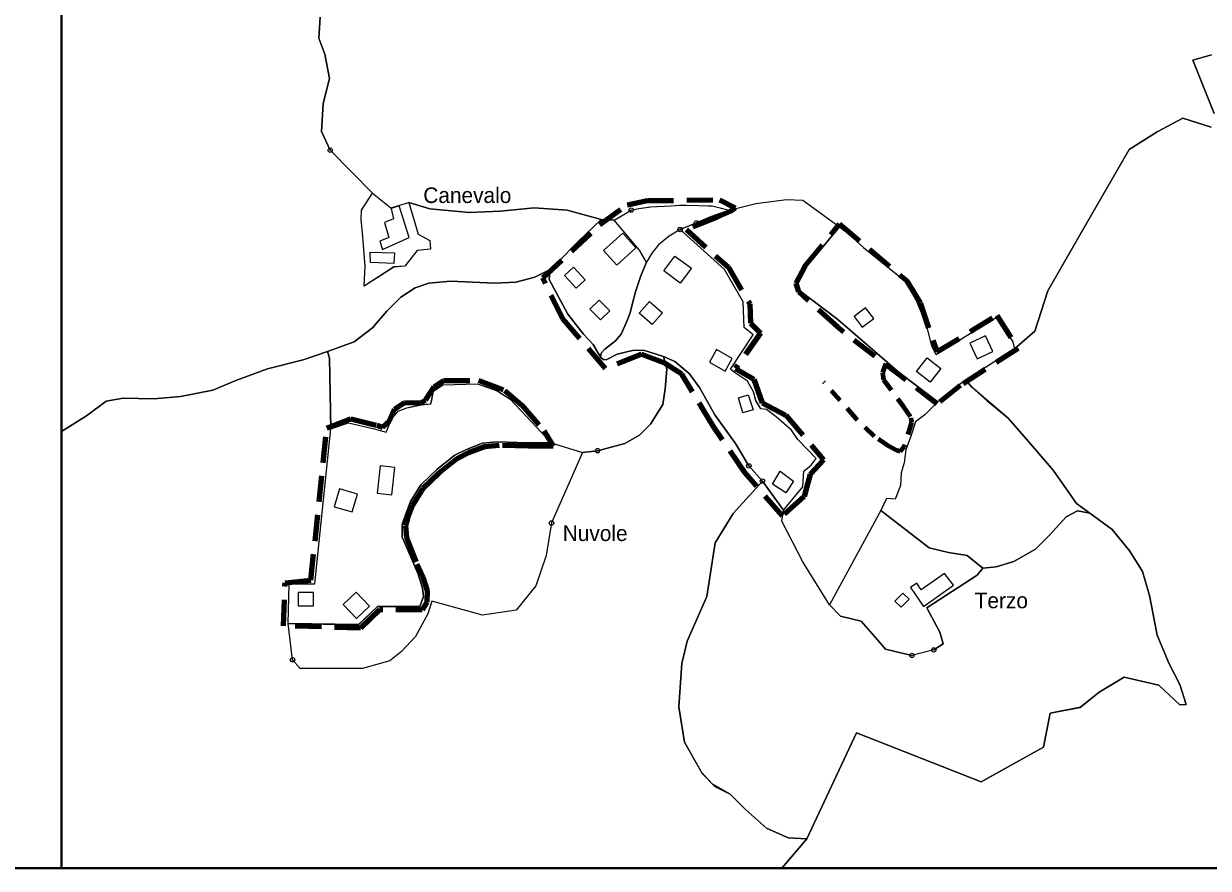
# Model space of a CAD drawing. Extents: x 650468 to 655025, y 889970 to 891591.
# Drawn here: x 653594 to 654354, y 889970 to 890512 of the extents above; entities that cross this region are included whole.
import ezdxf
from ezdxf.enums import TextEntityAlignment as Align

# ---------------------------------------------------------------- set-up
doc = ezdxf.new("R2010")
doc.units = 0
doc.header["$LTSCALE"] = 5.6
doc.header["$PDMODE"] = 32
doc.header["$PDSIZE"] = 2.8
doc.linetypes.add('MEDIUM_DASHED', pattern=[4.5, 3, -1.5])
doc.linetypes.add('SHORT_DASHED', pattern=[2.7, 1.5, -1.2])
for name, color, linetype, lineweight in [('11', 7, 'Continuous', 25), ('14', 7, 'Continuous', 25), ('2', 7, 'Continuous', 25), ('31', 7, 'Continuous', 25), ('35', 7, 'Continuous', 25), ('36', 7, 'Continuous', 25), ('37', 7, 'Continuous', 25), ('41', 7, 'SHORT_DASHED', 80), ('6', 7, 'Continuous', 25), ('61', 7, 'Continuous', 35), ('7', 7, 'MEDIUM_DASHED', 100), ('9', 7, 'Continuous', 25)]:
    doc.layers.add(name, color=color, linetype=linetype, lineweight=lineweight)
doc.layers.add('60', color=7, linetype='Continuous')

msp = doc.modelspace()

# ---------------------------------------------------------------- linework, layer by layer
at = {"layer": '11'}
for points in [[(654015.34, 890379.71), (654008.32, 890375.49), (654001.4, 890369.97), (653997.18, 890364.53), (653993.72, 890358.73), (653990.16, 890350.02), (653986.78, 890339.61), (653984.63, 890331.65), (653983.23, 890326.31), (653981.46, 890321.28), (653977.45, 890312.51), (653973.87, 890308.32), (653966.99, 890302.99)], [(654218.25, 890323.16), (654229.03, 890307.56), (654229.91, 890303.04), (654198.72, 890283.08), (654195.3, 890280.61), (654180.75, 890269.05), (654156.11, 890287.63), (654116.57, 890321.87), (654091.94, 890340.61), (654090.84, 890344.9), (654096.91, 890356.41), (654117.62, 890381.5), (654122.22, 890377.99)], [(654122.22, 890377.99), (654133.07, 890368.1), (654155.04, 890350.33), (654160.24, 890346.09), (654163.25, 890340.52), (654166.8, 890334.15), (654171.18, 890323.81), (654173.64, 890316.91), (654176.1, 890307.63), (654176.92, 890304.71), (654179.5, 890299.55), (654218.25, 890323.16)], [(654050.83, 890242.42), (654059.49, 890228), (654068.24, 890218.2), (654081.71, 890199.46), (654094.14, 890214.5), (654094.69, 890224.68), (654099.45, 890228.37), (654102.81, 890232.73), (654091, 890244.97), (654086.85, 890250.82), (654077.02, 890259.43), (654070.74, 890264.22), (654067.26, 890264.59), (654064.08, 890269.84), (654062.53, 890275.47), (654058.61, 890282.27), (654050.18, 890287.97), (654047.81, 890290.11), (654062.33, 890312.09), (654056.57, 890316.85), (654055.81, 890333.25), (654043.85, 890353.99)], [(654180.75, 890269.04), (654156.11, 890287.62), (654116.57, 890321.86)], [(653966.99, 890302.99), (653964.7, 890300.24), (653964.33, 890297.86), (653965.9, 890296.23), (653967.99, 890296.02), (653974.89, 890299.67)], [(653974.89, 890299.67), (653984.83, 890302.11), (653991.93, 890302.32), (654004.66, 890298.28), (654012.08, 890295), (654021.13, 890287.34), (654027.77, 890278.34), (654037.73, 890260.72), (654050.83, 890242.42)]]:
    msp.add_lwpolyline(points, dxfattribs=at)
for points in [[(654004.95, 890353.09), (654012.08, 890362.67), (654022.6, 890354.84), (654015.48, 890345.26)], [(653995.74, 890333.49), (654004.09, 890326.14), (653997.49, 890318.64), (653989.14, 890325.98)], [(654127.04, 890323.94), (654132.25, 890317.02), (654139.67, 890322.6), (654134.47, 890329.52)], [(654201.34, 890306.81), (654206, 890296.71), (654216.01, 890301.33), (654211.35, 890311.43)], [(654038.77, 890302.63), (654034.23, 890294.5), (654044.3, 890288.87), (654048.85, 890296.99)], [(654167.19, 890288.47), (654174.05, 890297.25), (654182.73, 890290.47), (654175.87, 890281.69)], [(653818.99, 890251.8), (653826.8, 890249.54), (653830.13, 890257.92), (653834.33, 890263.15), (653840.03, 890265.19), (653849.32, 890267.23), (653855.32, 890267.81), (653855.92, 890270.13), (653857.12, 890275.95), (653863.11, 890280.02), (653885.3, 890280.6), (653897.89, 890276.24), (653906.29, 890270.72), (653920.08, 890256.17), (653932.67, 890242.79), (653916.78, 890242.79), (653897.89, 890243.37), (653888.6, 890242.5), (653878.7, 890238.72), (653870.82, 890234.82), (653859.33, 890225.8), (653848.94, 890215.72), (653842.38, 890205.1), (653839.1, 890196.61), (653836.91, 890190.25), (653836.91, 890182.29), (653842.93, 890168.49), (653847.3, 890158.41), (653850.04, 890149.39), (653850.58, 890144.08), (653848.4, 890137.72), (653821.05, 890137.72), (653809.02, 890126.04), (653763.88, 890126.71), (653764.44, 890152.22), (653780.83, 890152.24), (653791.1, 890251.8), (653802.58, 890255.51)], [(654052.96, 890271.66), (654059.11, 890273.66), (654062.18, 890263.97), (654055.58, 890262.13)], [(653822.91, 890227.99), (653820.99, 890210.43), (653830.3, 890209.41), (653832.22, 890226.97)], [(654074.58, 890216.33), (654079.5, 890224.48), (654088.1, 890218.18), (654083.19, 890210.65)], [(653796.68, 890213.14), (653793.38, 890201.7), (653804.9, 890198.38), (653808.2, 890209.82)], [(653770.26, 890146.59), (653770.26, 890138.08), (653780.14, 890138.08), (653780.14, 890146.59)], [(653799.06, 890138.97), (653807.56, 890129.92), (653815.96, 890137.81), (653807.47, 890146.86)]]:
    msp.add_lwpolyline(points, close=True, dxfattribs=at)
msp.add_point((654015.34, 890379.71), dxfattribs=at)
at = {"layer": '14'}
msp.add_line((654025.89, 890383.92), (654015.34, 890379.7), dxfattribs=at)
for points in [[(654015.34, 890379.7), (654008.32, 890375.48), (654001.4, 890369.96), (653997.18, 890364.52), (653993.72, 890358.72), (653989.23, 890366.42), (653973.05, 890385.72), (653984, 890392.17)], [(653984, 890392.17), (653988.89, 890393.27), (653995.23, 890394.02), (653996.29, 890394.22), (654009.32, 890394.93), (654014.95, 890395.38), (654019.18, 890395.38), (654027.29, 890395.11), (654033.5, 890394.93), (654035.85, 890394.93), (654039.45, 890394.15)], [(654039.45, 890394.15), (654046.79, 890392.05), (654034.79, 890387.79), (654025.89, 890383.92)]]:
    msp.add_lwpolyline(points, dxfattribs=at)
for p in [(653984, 890392.17), (654025.89, 890383.92), (654015.34, 890379.7)]:
    msp.add_point(p, dxfattribs=at)
at = {"layer": '2'}
for points in [[(653817.94, 890402.98), (653829.77, 890393.69), (653841.23, 890397.15), (653847.17, 890376.66), (653854.67, 890372.66), (653855.17, 890367.15), (653846.67, 890366.15), (653838.68, 890356.15), (653831.68, 890355.65), (653812.48, 890343.43), (653813.21, 890355.99), (653811.69, 890375.16), (653810.69, 890386.16), (653810.84, 890392.05)], [(653829.83, 890393.26), (653831.47, 890386.52), (653825.72, 890384.16), (653828.38, 890374.5), (653822.55, 890372.31), (653824.37, 890366.85), (653841.48, 890374.68), (653835.11, 890394.9)], [(653816.49, 890365.23), (653832.14, 890364.69), (653831.6, 890357.95), (653816.67, 890358.5)], [(654170.15, 890148.38), (654167.26, 890152.7), (654163.27, 890149.94), (654171.57, 890137.59), (654190.84, 890151.47), (654185.18, 890158.88)]]:
    msp.add_lwpolyline(points, close=True, dxfattribs=at)
for points in [[(654178.16, 890109.82), (654184.15, 890113.82), (654182.15, 890121.32), (654173.66, 890136.83), (654206.14, 890157.84), (654209.64, 890162.34), (654199.65, 890170.34), (654187.65, 890172.34), (654175.16, 890175.34), (654144.17, 890199.35), (654111.19, 890138.83), (654118.32, 890131.45), (654131.68, 890128.33)], [(654131.68, 890128.33), (654142.17, 890116.32), (654147.17, 890110.32), (654164.16, 890106.32)]]:
    msp.add_lwpolyline(points, dxfattribs=at)
for p in [(654178.16, 890109.82), (654164.16, 890106.32)]:
    msp.add_point(p, dxfattribs=at)
at = {"layer": '31'}
for points in [[(654055.81, 890333.24), (654043.85, 890353.98), (654015.34, 890379.7), (654034.79, 890387.79), (654046.79, 890392.05), (654064.02, 890396.31), (654083.57, 890399.03), (654094.21, 890398.64), (654117.62, 890381.49), (654096.91, 890356.4), (654090.84, 890344.89), (654091.94, 890340.6), (654116.57, 890321.86)], [(654077.02, 890259.42), (654070.74, 890264.21), (654067.26, 890264.58), (654064.08, 890269.83), (654062.53, 890275.46), (654058.61, 890282.26), (654050.18, 890287.96), (654047.81, 890290.1), (654062.32, 890312.07), (654056.57, 890316.84), (654055.81, 890333.24)], [(654116.57, 890321.86), (654156.11, 890287.62), (654180.75, 890269.04), (654172.48, 890260.79), (654166.41, 890256.16), (654163.23, 890246.32), (654160.34, 890238.22), (654159.19, 890229.83), (654157.16, 890223.47), (654156.87, 890215.37), (654153.4, 890206.69), (654147.91, 890206.98), (654144.17, 890199.34)], [(654091, 890244.96), (654086.85, 890250.81), (654077.02, 890259.42)], [(654144.17, 890199.34), (654111.19, 890138.82), (654094.08, 890166.41), (654080.71, 890192.55), (654081.71, 890199.45), (654094.14, 890214.49), (654094.69, 890224.67), (654099.45, 890228.36), (654102.81, 890232.72), (654091, 890244.96)]]:
    msp.add_lwpolyline(points, dxfattribs=at)
msp.add_lwpolyline([(654147.91, 890206.98), (654144.17, 890199.34), (654175.16, 890175.33), (654187.65, 890172.33), (654199.65, 890170.33), (654209.64, 890162.33), (654218.14, 890163.2), (654229.49, 890166.48), (654243.53, 890174.55), (654252.49, 890183.52), (654263.25, 890195.17), (654270.48, 890199.06), (654278.3, 890197.58), (654269.71, 890203.72), (654254.8, 890225.21), (654238.98, 890243.63), (654225.87, 890258.54), (654202.82, 890278.27), (654198.75, 890283.1), (654195.3, 890280.6), (654180.75, 890269.04), (654172.48, 890260.79), (654166.41, 890256.16), (654163.23, 890246.32), (654160.34, 890238.22), (654159.19, 890229.83), (654157.16, 890223.47), (654156.87, 890215.37), (654153.4, 890206.69)], close=True, dxfattribs=at)
at = {"layer": '35'}
for p, q in [((653964.64, 890386.06), (653973.05, 890385.72)), ((653931.33, 890347.71), (653932.07, 890354.07)), ((653788.94, 890301.35), (653790.24, 890297.07))]:
    msp.add_line(p, q, dxfattribs=at)
for points in [[(653931.33, 890347.71), (653932.07, 890354.07), (653922.21, 890349.15), (653910, 890345.87), (653896.19, 890345.29), (653867.97, 890346.45), (653854.12, 890345.29), (653845.35, 890342.21), (653836.11, 890336.28), (653827.14, 890327.23), (653817.98, 890316.61), (653806.18, 890307.6), (653788.95, 890301.36)], [(653959.57, 890305.91), (653953.4, 890312.44), (653943.37, 890325.35), (653931.33, 890347.71)], [(653952.62, 890236.52), (653962.37, 890237.73), (653979.91, 890242.32), (653989.36, 890247.72), (653996.37, 890254.74), (654004.2, 890267.43), (654005.82, 890277.42), (654006.9, 890290.11), (654004.66, 890298.27), (653991.93, 890302.31), (653984.83, 890302.1), (653974.89, 890299.66), (653967.99, 890296.01), (653965.9, 890296.22), (653964.33, 890297.85), (653959.57, 890305.91)], [(653790.24, 890297.07), (653791.13, 890251.82), (653802.56, 890255.55), (653818.97, 890251.84), (653826.78, 890249.58), (653830.11, 890257.96), (653834.31, 890263.19), (653840.01, 890265.23), (653849.3, 890267.27), (653855.3, 890267.85), (653857.1, 890275.99), (653863.09, 890280.06), (653885.28, 890280.64), (653897.87, 890276.28), (653906.27, 890270.76), (653920.06, 890256.21), (653932.65, 890242.83), (653932.68, 890242.83), (653932.68, 890242.82), (653952.62, 890236.52)], [(653856.06, 890141.13), (653853.36, 890132.98), (653845.55, 890118.41), (653836.54, 890108.8), (653829.15, 890102.81), (653811.44, 890097.86), (653771.51, 890097.86), (653766.65, 890103.47), (653763.86, 890126.75), (653763.88, 890126.7), (653809.02, 890126.03), (653821.05, 890137.71), (653848.4, 890137.71), (653850.58, 890144.07), (653850.04, 890149.38), (653847.3, 890158.4), (653842.93, 890168.48), (653836.91, 890182.28), (653836.91, 890190.24), (653839.1, 890196.6), (653842.38, 890205.09), (653848.94, 890215.71), (653859.33, 890225.79), (653870.82, 890234.81), (653878.7, 890238.71), (653888.6, 890242.49), (653897.89, 890243.36), (653916.78, 890242.78), (653932.67, 890242.78), (653932.68, 890242.82), (653952.62, 890236.52)], [(653952.62, 890236.52), (653932.82, 890191.3), (653929.47, 890170.51), (653922.78, 890151.01), (653910.05, 890135.42), (653888.62, 890132.17), (653856.06, 890141.13)], [(654111.19, 890138.82), (654094.08, 890166.41), (654080.71, 890192.55), (654081.71, 890199.45), (654068.24, 890218.19), (654049.33, 890197.35), (654037.95, 890178.5), (654032.59, 890144.06), (654019.86, 890115.47), (654016.52, 890101.17), (654014.51, 890073.23), (654018.17, 890050.66), (654029.61, 890030.55), (654037.65, 890022.05), (654047.54, 890017.25), (654057.28, 890007.35), (654070.88, 889995.29)], [(654070.88, 889995.29), (654084.8, 889989.1), (654096.73, 889988.47), (654128.69, 890056.58), (654208.52, 890025.08), (654248.58, 890047.42), (654252.88, 890069.18), (654272.11, 890072.87), (654284.35, 890082.64), (654300.38, 890092.38), (654322.7, 890087.22), (654336.11, 890074.55), (654340.1, 890074.77), (654336.08, 890087.71), (654329.3, 890100.86), (654321.62, 890119.28), (654316.65, 890144.72), (654312.13, 890160.07), (654303.99, 890173.23), (654292.77, 890187.05), (654278.3, 890197.58)], [(654263.25, 890195.17), (654252.49, 890183.52), (654243.53, 890174.55), (654229.49, 890166.48), (654218.14, 890163.2), (654209.64, 890162.33), (654206.14, 890157.83), (654173.66, 890136.82), (654182.15, 890121.31), (654184.15, 890113.81), (654178.16, 890109.81), (654164.16, 890106.31)], [(654278.3, 890197.58), (654270.48, 890199.06), (654263.25, 890195.17)], [(654164.16, 890106.31), (654147.17, 890110.31), (654142.17, 890116.31), (654131.68, 890128.32), (654118.32, 890131.44), (654111.19, 890138.82)]]:
    msp.add_lwpolyline(points, dxfattribs=at)
msp.add_point((654164.16, 890106.31), dxfattribs=at)
at = {"layer": '36'}
msp.add_line((654068.24, 890218.19), (654059.49, 890227.99), dxfattribs=at)
for points in [[(653786.19, 890700.26), (653771.25, 890705.76), (653723.84, 890725.75), (653661.66, 890751.68), (653637.45, 890759.68), (653618.27, 890761.81), (653618.27, 890249.95)], [(653790.8, 890430.55), (653785.14, 890442.55), (653786.17, 890460.55), (653790.29, 890476.55), (653787.43, 890492.37), (653783.48, 890502.65), (653784.27, 890516.11)], [(654356.52, 890491.95), (654344.46, 890488.33), (654358.17, 890454.25)], [(654356.22, 890445.34), (654338.14, 890451.18), (654321.55, 890442.46), (654303.67, 890431.15), (654268.91, 890371.05), (654251.39, 890340.44), (654243.16, 890314.51), (654229.91, 890303.04), (654198.75, 890283.1), (654202.82, 890278.27), (654212.31, 890269.94), (654225.87, 890258.54), (654238.98, 890243.63), (654254.8, 890225.21), (654269.71, 890203.72), (654278.3, 890197.58)], [(653810.84, 890392.04), (653817.94, 890402.97), (653790.8, 890430.55)], [(653750.57, 890290.26), (653773.5, 890295.95), (653788.94, 890301.35), (653806.18, 890307.6), (653817.98, 890316.61), (653827.14, 890327.23), (653836.11, 890336.28), (653845.35, 890342.21), (653854.12, 890345.29), (653867.97, 890346.45), (653896.19, 890345.29), (653910, 890345.87), (653922.21, 890349.15), (653932.07, 890354.07), (653937.04, 890359.04), (653949.74, 890371.85), (653964.64, 890386.06), (653942.81, 890392.06), (653921.68, 890393.56), (653900.04, 890391.56), (653879.95, 890390.56), (653854.7, 890393.06), (653841.23, 890397.14), (653847.17, 890376.65), (653854.67, 890372.65), (653855.17, 890367.14), (653846.67, 890366.14), (653838.68, 890356.14), (653831.68, 890355.64), (653812.48, 890343.42), (653813.21, 890355.98), (653811.69, 890375.15), (653810.69, 890386.15), (653810.84, 890392.04)], [(653788.94, 890301.35), (653773.5, 890295.95), (653750.57, 890290.26)], [(653766.65, 890103.47), (653763.86, 890126.75), (653764.47, 890152.24), (653780.86, 890152.26), (653791.13, 890251.82), (653790.24, 890297.07), (653788.94, 890301.35)], [(654059.49, 890227.99), (654050.85, 890242.43), (654037.73, 890260.71), (654027.79, 890278.35), (654021.13, 890287.33), (654012.08, 890294.99), (654004.66, 890298.27), (654006.9, 890290.11)], [(653750.57, 890290.26), (653730.14, 890282.83), (653715.47, 890276.64), (653694.74, 890272.42), (653677.48, 890270.94)], [(653694.74, 890272.42), (653715.47, 890276.64), (653730.14, 890282.83), (653750.57, 890290.26)], [(654006.9, 890290.11), (654005.82, 890277.42), (654004.2, 890267.43), (653996.37, 890254.74), (653989.36, 890247.72), (653979.91, 890242.32), (653962.37, 890237.73)], [(653677.48, 890270.94), (653657.86, 890271.37), (653646.97, 890269.61), (653634.33, 890260.12), (653618.27, 890249.95), (653618.27, 889969.62)], [(653618.27, 890249.95), (653634.33, 890260.12), (653646.97, 890269.61)], [(653646.97, 890269.61), (653657.86, 890271.37), (653677.48, 890270.94), (653694.74, 890272.42)], [(653962.37, 890237.73), (653952.62, 890236.52), (653932.82, 890191.3)], [(654014.55, 890073), (654014.51, 890073.23), (654016.52, 890101.17), (654019.86, 890115.47), (654032.59, 890144.06), (654037.95, 890178.5), (654049.33, 890197.35), (654068.24, 890218.19)], [(654278.3, 890197.58), (654292.77, 890187.05), (654303.99, 890173.23), (654312.13, 890160.07), (654316.65, 890144.72), (654321.62, 890119.28), (654329.3, 890100.86), (654336.08, 890087.71), (654340.1, 890074.77), (654336.11, 890074.55), (654322.7, 890087.22), (654300.38, 890092.38), (654284.35, 890082.64), (654272.27, 890073)], [(653932.82, 890191.3), (653929.47, 890170.51), (653922.78, 890151.01), (653910.05, 890135.42), (653888.62, 890132.17), (653856.06, 890141.13), (653853.36, 890132.98), (653845.55, 890118.41), (653836.54, 890108.8), (653829.15, 890102.81), (653811.44, 890097.86), (653771.51, 890097.86), (653766.65, 890103.47)], [(653618.27, 889969.62), (654080.65, 889969.62), (654096.73, 889988.47), (654084.8, 889989.1), (654070.88, 889995.29), (654057.28, 890007.35), (654047.54, 890017.25), (654035.92, 890023.88), (654029.19, 890031.3), (654018.17, 890050.66), (654014.55, 890073)], [(654272.27, 890073), (654252.88, 890069.18), (654248.58, 890047.42), (654217.72, 890030.21), (654208.52, 890025.08), (654128.69, 890056.58), (654096.73, 889988.47), (654080.65, 889969.62), (655025.2, 889969.62)]]:
    msp.add_lwpolyline(points, dxfattribs=at)
for p in [(653790.8, 890430.55), (653962.37, 890237.73), (654059.49, 890227.99), (654068.24, 890218.19), (653932.82, 890191.3), (653766.65, 890103.47)]:
    msp.add_point(p, dxfattribs=at)
at = {"layer": '37'}
for points in [[(653784.27, 890516.11), (653783.48, 890502.65), (653787.43, 890492.37), (653790.29, 890476.55), (653786.17, 890460.55), (653785.14, 890442.55), (653790.8, 890430.55)], [(654358.17, 890454.25), (654344.46, 890488.33), (654356.52, 890491.95)], [(654218.25, 890323.15), (654229.03, 890307.55), (654229.56, 890304.86), (654229.91, 890303.04), (654243.16, 890314.51), (654251.39, 890340.44), (654268.91, 890371.05), (654303.67, 890431.15), (654321.55, 890442.46), (654338.14, 890451.18), (654356.22, 890445.34)], [(653790.8, 890430.55), (653817.94, 890402.97), (653829.77, 890393.68), (653841.23, 890397.14), (653854.7, 890393.06), (653879.95, 890390.56), (653900.04, 890391.56), (653921.68, 890393.56), (653942.81, 890392.06), (653964.64, 890386.06), (653973.05, 890385.72), (653984, 890392.17), (653988.89, 890393.27), (653996.29, 890394.22), (654009.32, 890394.93), (654014.95, 890395.38), (654027.29, 890395.11), (654033.5, 890394.93), (654035.85, 890394.93), (654046.79, 890392.05), (654064.02, 890396.31), (654083.57, 890399.03), (654094.21, 890398.64), (654117.62, 890381.49), (654122.22, 890377.98), (654133.07, 890368.09), (654155.04, 890350.32), (654160.24, 890346.08), (654163.25, 890340.51), (654166.8, 890334.14), (654171.18, 890323.8), (654173.64, 890316.9), (654176.1, 890307.62), (654176.92, 890304.7), (654179.5, 890299.54), (654218.25, 890323.15)]]:
    msp.add_lwpolyline(points, dxfattribs=at)
msp.add_point((653790.8, 890430.55), dxfattribs=at)
at = {"layer": '41'}
msp.add_lwpolyline([(654147.48, 890293.42), (654145.32, 890287.86), (654145.94, 890283.23), (654158.27, 890266.57), (654163.52, 890258.85), (654163.82, 890256.08), (654159.2, 890240.34), (654156.73, 890237.25), (654154.57, 890237.87), (654149.64, 890240.34), (654140.08, 890246.82), (654128.05, 890258.54), (654107.69, 890281.69)], dxfattribs=at)
at = {"layer": '6'}
msp.add_lwpolyline([(654157.26, 890137.21), (654153.25, 890141.13), (654158.32, 890146.32), (654162.33, 890142.41)], close=True, dxfattribs=at)
at = {"layer": '61', "lineweight": 40}
for points in [[(653618.27, 891591.08), (653618.27, 889969.62), (652568.28, 889969.62), (652568.28, 891591.08)], [(653618.27, 891591.08), (655025.2, 891591.08), (655025.2, 889969.62), (653618.27, 889969.62)]]:
    msp.add_lwpolyline(points, close=True, dxfattribs=at)
at = {"layer": '7'}
for points in [[(653927.16, 890348.71), (653963.75, 890382.62), (653981.5, 890395.54), (653994.42, 890398.24), (654040.69, 890398.77), (654050.75, 890393.63), (654047.52, 890391.24), (654039.08, 890387.74), (654019.4, 890379.66), (654046.34, 890355.58), (654060.06, 890332.02), (654060.6, 890319.64), (654067.05, 890313.18), (654050.91, 890290.57), (654062.75, 890283.57), (654068.13, 890268.5), (654083.19, 890260.43), (654107.4, 890231.9), (654098.8, 890222.74), (654095.03, 890208.21), (654081.04, 890195.83), (654056.83, 890223.82), (654036.38, 890253.97), (654016.48, 890286.8), (654004.64, 890294.34), (653990.65, 890299.72), (653967.52, 890290.57), (653940.08, 890322.33)], [(654089.87, 890345.27), (654096.05, 890356.98), (654117.69, 890383.27), (654160.65, 890346.93), (654169.48, 890332.57), (654180.09, 890301.09), (654218.62, 890324.51), (654232.31, 890303.41), (654195.21, 890279.55), (654180.42, 890267.72), (654116.55, 890316.95), (654091.52, 890339.64)], [(653820.71, 890254.08), (653824.25, 890252.8), (653828.86, 890256.96), (653832.02, 890264.38), (653838.57, 890268.57), (653848.9, 890268.42), (653851.93, 890270.18), (653856.11, 890276.3), (653857.6, 890278.65), (653863.59, 890282.72), (653886.04, 890282.74), (653902.77, 890276.3), (653913.72, 890266.96), (653927.87, 890250.54), (653933.98, 890240.54), (653918.09, 890240.54), (653899.2, 890241.12), (653889.91, 890240.25), (653880.01, 890236.47), (653872.13, 890232.57), (653860.64, 890223.55), (653850.25, 890213.47), (653843.69, 890202.85), (653840.41, 890194.36), (653839.06, 890189.69), (653839.7, 890181.96), (653846.46, 890164.89), (653850.32, 890156.52), (653852.92, 890147.82), (653852.88, 890140.54), (653849.71, 890135.47), (653822.36, 890135.47), (653810.33, 890123.79), (653760.86, 890125.29), (653761.82, 890152.98), (653778.39, 890154.67), (653788.66, 890252.13), (653803.99, 890258.13)]]:
    msp.add_lwpolyline(points, close=True, dxfattribs=at)
at = {"layer": '9'}
msp.add_line((653931.33, 890347.71), (653931.33, 890347.7), dxfattribs=at)
for points in [[(653964.33, 890297.85), (653964.7, 890300.23), (653966.99, 890302.98), (653973.87, 890308.31), (653977.45, 890312.5), (653981.46, 890321.27), (653983.23, 890326.3), (653984.63, 890331.64), (653986.78, 890339.6), (653990.16, 890350.01), (653993.72, 890358.72), (653989.23, 890366.42), (653973.05, 890385.72), (653964.64, 890386.06), (653949.74, 890371.85), (653937.04, 890359.04), (653932.07, 890354.07), (653931.33, 890347.71)], [(653931.33, 890347.7), (653943.37, 890325.35), (653953.4, 890312.44), (653959.57, 890305.91), (653964.33, 890297.85)]]:
    msp.add_lwpolyline(points, dxfattribs=at)
for points in [[(653978.51, 890377.43), (653966.17, 890366.26), (653974.72, 890356.81), (653987.06, 890367.98)], [(653954.52, 890347.36), (653948.76, 890342.04), (653941.25, 890350.17), (653947.01, 890355.49)], [(653963.32, 890334.45), (653970.18, 890327.53), (653964.36, 890321.76), (653957.5, 890328.68)]]:
    msp.add_lwpolyline(points, close=True, dxfattribs=at)

# ---------------------------------------------------------------- texts
at = {"layer": '60'}
for s, p in [('Canevalo', (653878.79, 890396.73)), ('Nuvole', (653960.86, 890179.72)), ('Terzo', (654221.55, 890136.57))]:
    msp.add_text(s, height=10, dxfattribs=at).set_placement(p, align=Align.CENTER)

doc.saveas('drawing.dxf')
